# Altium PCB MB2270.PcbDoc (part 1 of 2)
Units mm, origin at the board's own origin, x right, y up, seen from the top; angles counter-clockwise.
Board outline 55.25 x 31 mm, 4 copper layers (Top Layer, Layer 1, Layer 2, Bottom Layer), stack 0.598 mm thick; 43 components, 44 nets, 187 pads, 892 vias.
Unrouted connection lines stored in the file: 111.
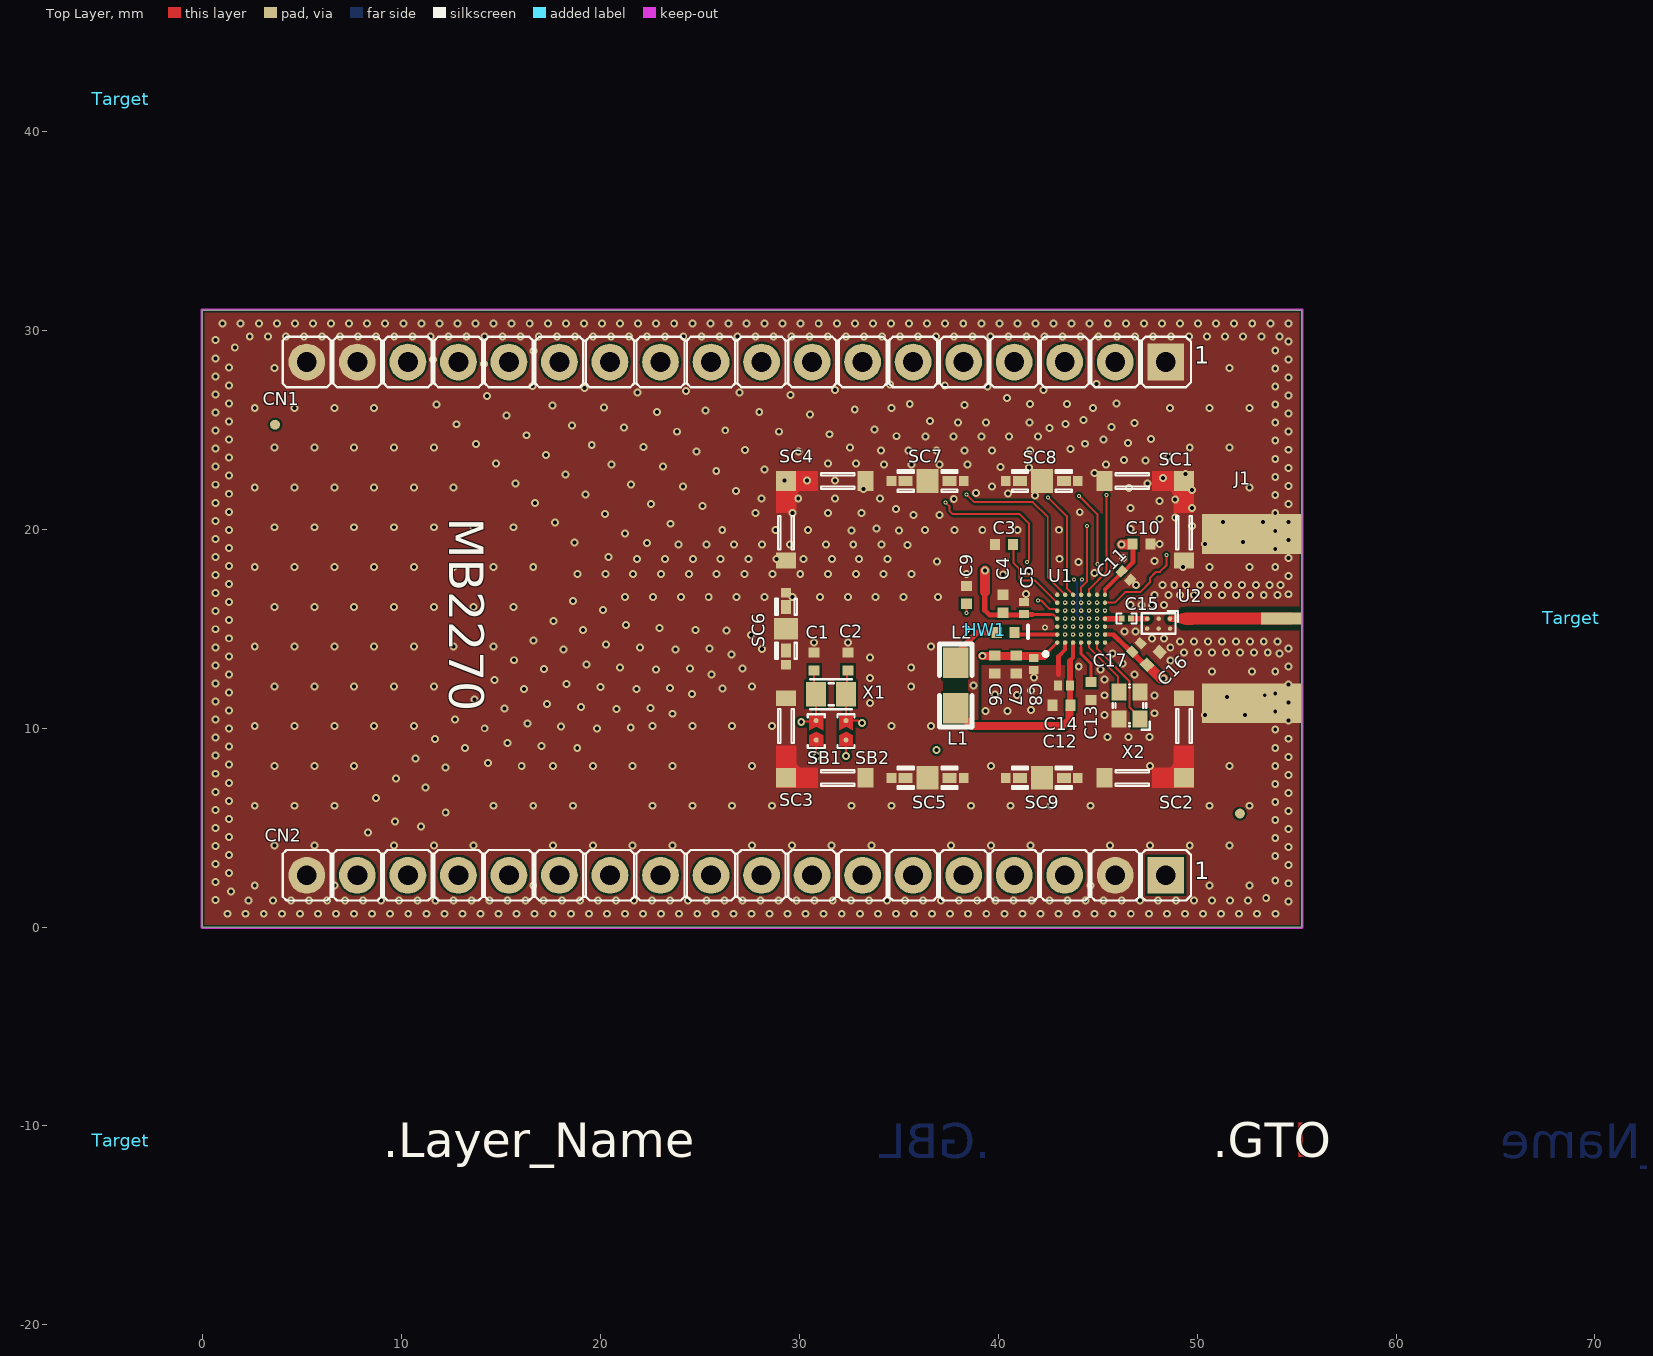
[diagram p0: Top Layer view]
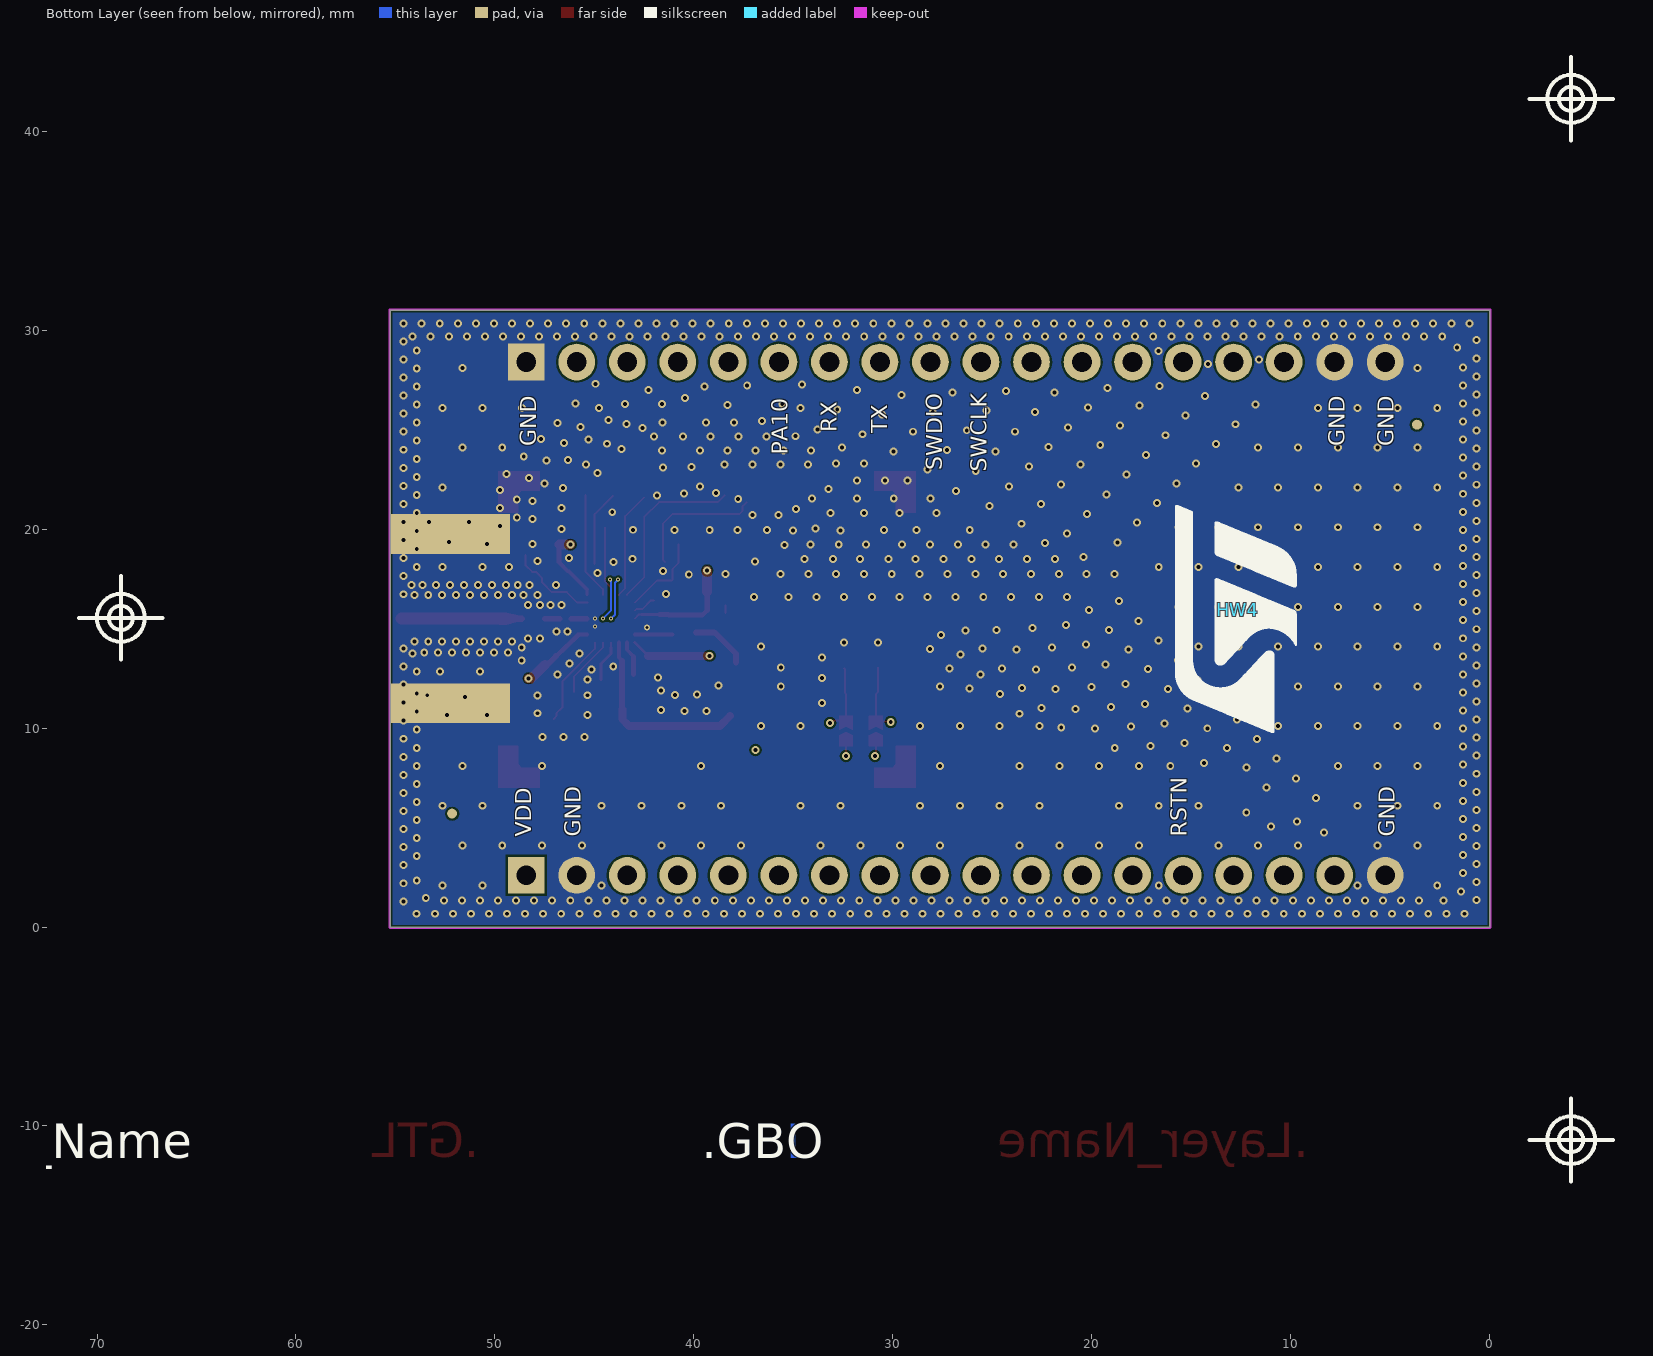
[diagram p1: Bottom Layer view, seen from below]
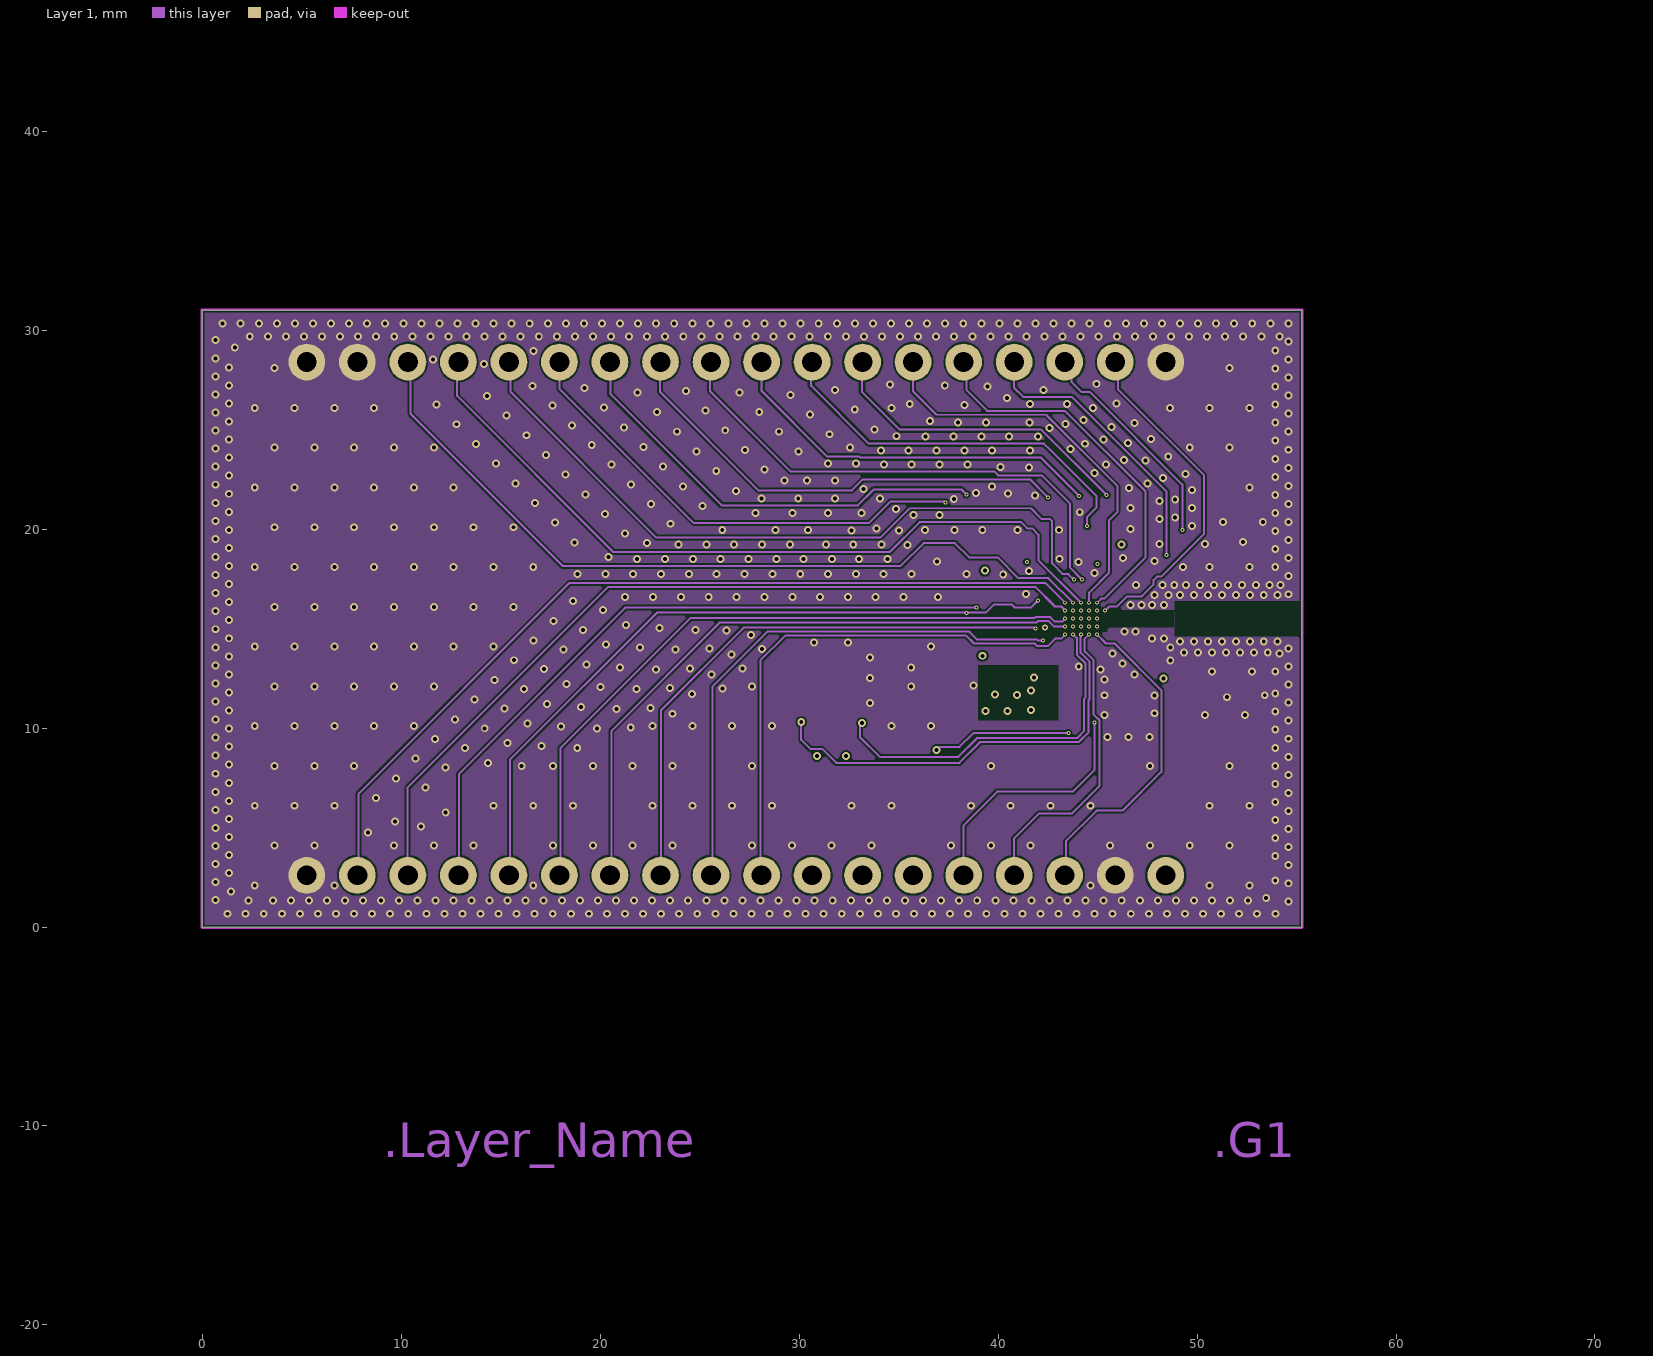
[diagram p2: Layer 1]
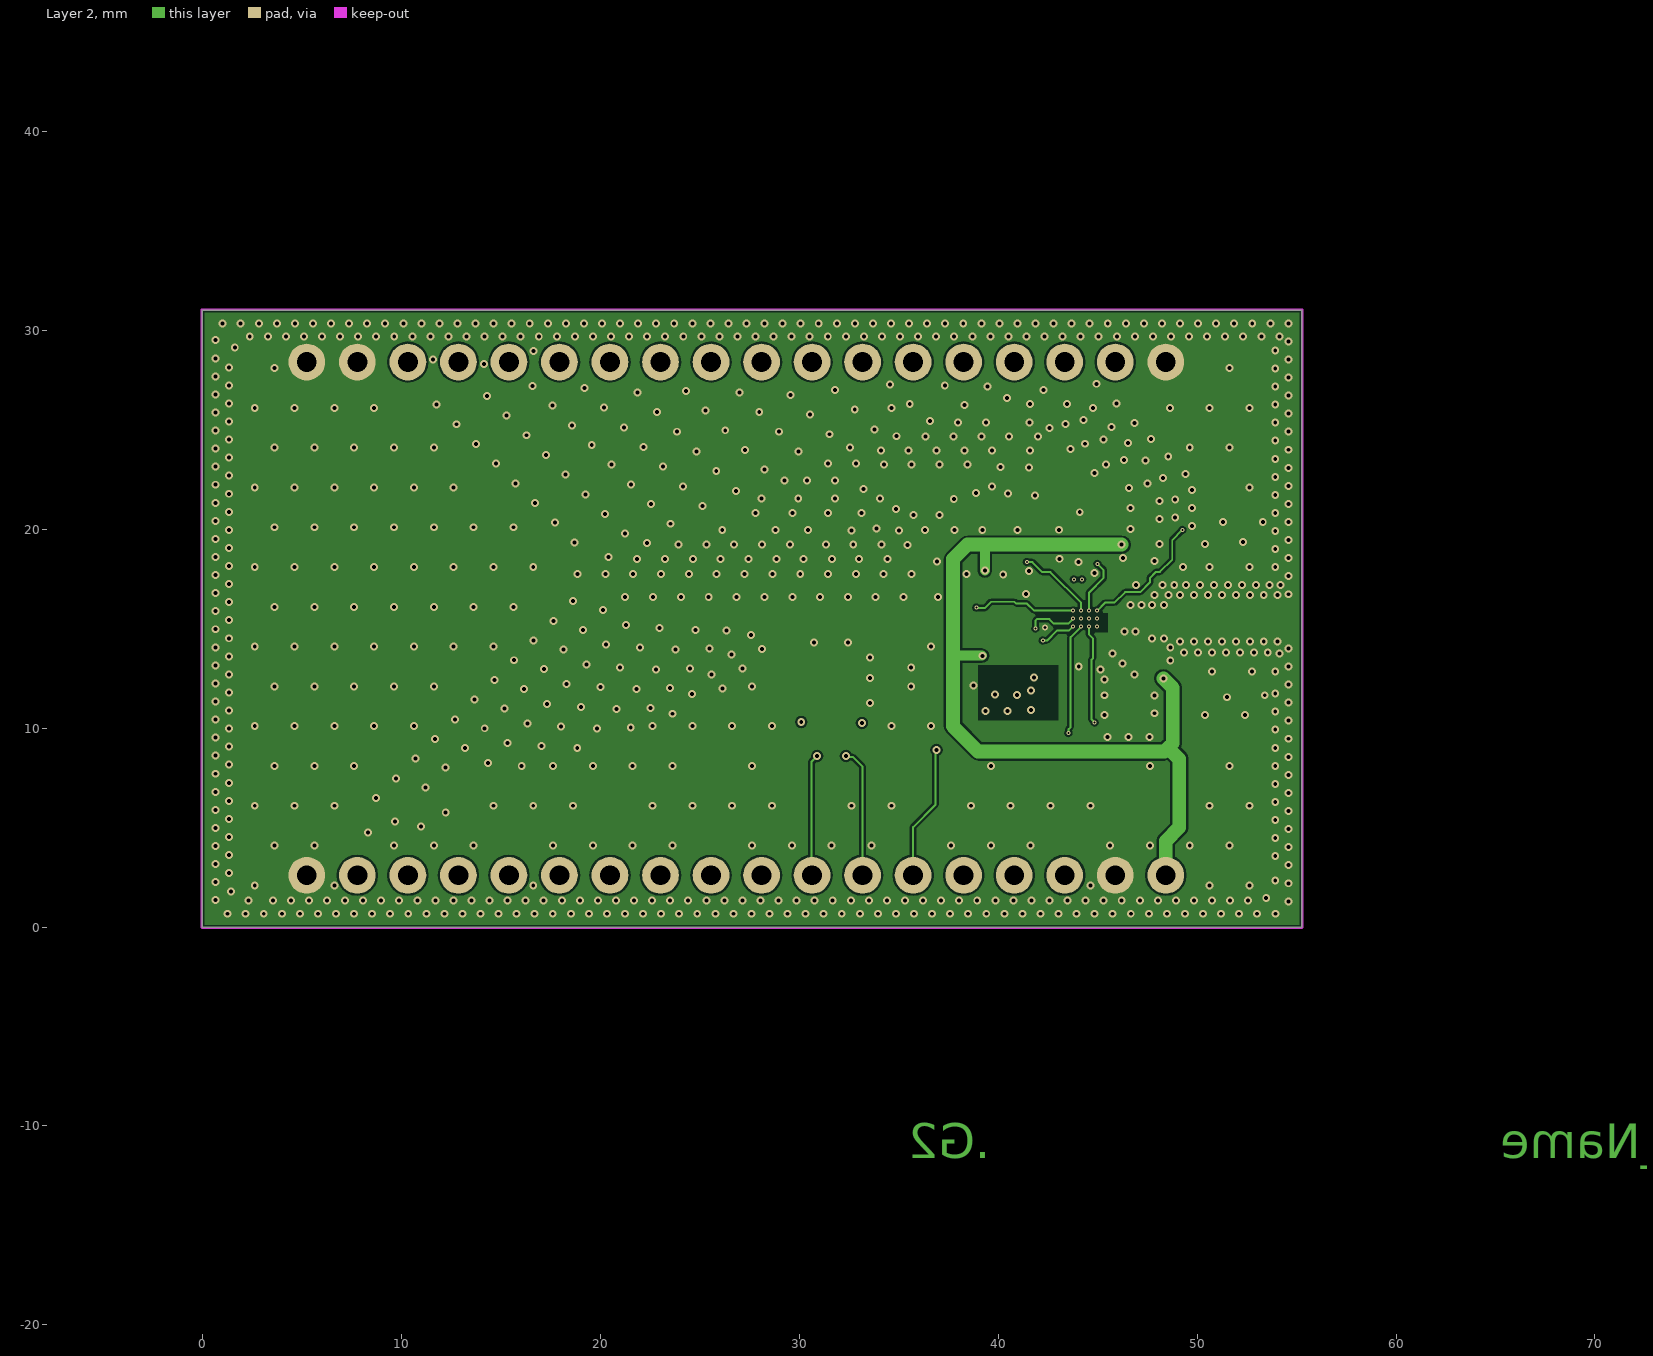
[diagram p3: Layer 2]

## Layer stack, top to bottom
Top Solder: solder mask 0.02, Solder Resist, Dk 3.5
Top Layer: signal copper 0.035
Dielectric 2: prepreg 0.102, TU-768 (1x2113), Dk 4.2
Layer 1: signal copper 0.035
Dielectric 1: dielectric 0.254, TU-768 (2x2116), Dk 4.3
Layer 2: signal copper 0.035
Dielectric 3: prepreg 0.102, TU-768 (1x2113), Dk 4.2
Bottom Layer: signal copper 0.035
Bottom Solder: solder mask 0.02, Solder Resist, Dk 3.5

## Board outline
0,0 55.25,0 55.25,31 0,31

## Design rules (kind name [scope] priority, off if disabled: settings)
Clearance Clearance_RF [InNet('NetJ1_1')] p1: gap=0.14 ignorepadtopadclearanceinfootprint=FALSE
Clearance [All] p2: gap=0.1 ignorepadtopadclearanceinfootprint=FALSE
HoleToHoleClearance [All] p1: gap=0.15 allowstackedmicrovias=TRUE
MinimumSolderMaskSliver [All] p1: minsoldermaskwidth=0
ParallelSegment [All] p1 off: limit=10 gap=0.3
PlaneClearance [All] p1: clearance=0
PlaneConnect [InNet('GND')] p1: planeconnectstyle=Direct reliefexpansion=0.508 reliefentries=4 reliefconductorwidth=0.254 reliefairgap=0.254
PolygonConnect [InNet('GND')] p1: connectstyle=Direct reliefconductorwidth=0.254 reliefentries=4 polygonreliefangle="90 Angle" airgapwidth=0.254
RoutingVias [All] p1: holewidth=0.2 width=0.4 viastyle="Through Hole" minholewidth=0.2 minwidth=0.4 maxholewidth=0.2 maxwidth=0.4
SilkToSilkClearance [All] p1: silktosilkclearance=0
SilkToSolderMaskClearance [IsPad] p1: minsilkscreentomaskgap=0 clearancetoexposedcopper=TRUE
SolderMaskExpansion [All] p1: expansion=0.102 istentingtop=FALSE
SupplyNets "Schematic Supply Nets" [InNet('VDD')] p1: voltage=0.000
Width [All] p1: maxlimit=0.7 minlimit=0.1 preferedwidth=0.1
24 further rules are at their usual default settings.

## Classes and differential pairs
component class STM32WB07_WLCSP49_RefBoard_IPD_4Layers: C1 C2 C3 C4 C5 C6 C7 C8 C9 C10 C11 C12 C13 C14 C15 C16 C17 CN1 CN2 J1 L1 L2 SB1 SB2 SC1 SC2 SC3 SC4 SC5 SC6 SC7 SC8 SC9 U1 U2 X1 X2

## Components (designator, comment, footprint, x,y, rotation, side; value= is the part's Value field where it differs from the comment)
C1 "Capacitor" C0402 30.75,13.35 r90 top value=8.2pF
C2 "Capacitor" C0402 32.45,13.35 r270 top value=8.2pF
C3 "Capacitor" C0402 40.297,19.219 r180 top value=0.22uF
C4 "Capacitor" C0402 40.25,16.25 r270 top value=1uF
C5 "Capacitor" C0201_H0P3 41.293,16.039 r270 top value=100nF
C6 "Capacitor" C0402 39.827,13.2 r90 top value=4.7uF
C7 "Capacitor" C0402 40.907,13.2 r90 top value=4.7uF
C8 "Capacitor" C0201_H0P3 41.788,13.219 r90 top value=100nF
C9 "Capacitor" C0402 38.4,16.7 r90 top value=10nF
C10 "Capacitor" C0402 47.2,19.25 r180 top value=1uF
C11 "Capacitor" C0201_H0P3 46.42,17.66 r135 top value=100nF
C12 "Capacitor" C0402 43.18,11.15 r0 top value=4.7uF
C13 "Capacitor" C0402 44.658,11.862 r270 top value=0.22uF
C14 "Capacitor" C0201_H0P3 43.3,12.15 r0 top value=100nF
C15 "Capacitor" 20p_capacitor_SMD_0201 46.444,15.5 r90 top locked value=20pF
C16 "Capacitor" C0402 47.8,13.5 r225 top value=1uF
C17 "Capacitor" C0201_H0P3 46.95,14.05 r225 top value=100nF
CN1 "Header 18x1" CON_SAMTEC_TSW-118-07-X-S 26.835,28.4 r180 top locked
CN2 "Header 18x1" CON_SAMTEC_TSW-118-07-X-S 26.835,2.6 r180 top locked
Designator16 "Comment" IMPEDANCE_TABLE 92.539,-28.797 r0 top
HW1 "S02-20150300" SHIELD_HARWIN_S02-20150300_15X20_H3 39.34,14.95 r90 top
HW4 "Logo" LOGO_ST 12.65,15.95 r90 bottom
J1 "SMA_connector" SMA_AMPHENOL_132415 54.225,15.5 r180 top
L1 "Inductor" 0805_COIL 37.869,10.999 r90 top value=10uH
L2 "Inductor" C0402 40.378,14.809 r0 top value=22nH
SB1 "SB_ON" SOLDER-BRIDGE_R0402-0R 30.85,9.85 r90 top value=0R
SB2 "SB_ON" SOLDER-BRIDGE_R0402-0R 32.35,9.85 r90 top value=0R
SC1 "Shield-clip_S0951-46R" CLIP_HARWIN_S0981-46R 49.337,22.418 r90 top locked value=S0981-46R
SC2 "Shield-clip_S0951-46R" CLIP_HARWIN_S0981-46R 49.337,7.5 r0 top locked value=S0981-46R
SC3 "Shield-clip_S0951-46R" CLIP_HARWIN_S0981-46R 29.337,7.5 r270 top locked value=S0981-46R
SC4 "Shield-clip_S0951-46R" CLIP_HARWIN_S0981-46R 29.337,22.418 r180 top locked value=S0981-46R
SC5 "Shield-clip_S0951-46R" CLIP_HARWIN_S0951-46R 36.448,7.5 r180 top locked value=S0951-46R
SC6 "Shield-clip_S0951-46R" CLIP_HARWIN_S0951-46R 29.337,14.993 r270 top locked value=S0951-46R
SC7 "Shield-clip_S0951-46R" CLIP_HARWIN_S0951-46R 36.448,22.418 r180 top locked value=S0951-46R
SC8 "Shield-clip_S0951-46R" CLIP_HARWIN_S0951-46R 42.198,22.418 r180 top locked value=S0951-46R
SC9 "Shield-clip_S0951-46R" CLIP_HARWIN_S0951-46R 42.198,7.5 r180 top locked value=S0951-46R
Target "" "Target PCB" -4.1,41.628 r90 top
Target "" "Target PCB" 68.8,15.54 r90 top
Target "" "Target PCB" -4.1,-10.71 r90 top
U1 "STM32WB07" STM32WB07_WLCSP49 44.169,15.5 r90 top locked
U2 "MLPF-WB55-01E3" ICC_CSPG_6BUMPS_1X1P60_P050-P0577 48.066,15.25 r270 top locked value=MLPF-NRG-01D3
X1 "XTAL_2_PINS" CRY_NX2012SA_2P 31.6,11.703 r0 top value=32.768kHz
X2 "XTAL_4_PINS" CRY_NX2016SA_4P 46.6,11.138 r90 top value=32MHz

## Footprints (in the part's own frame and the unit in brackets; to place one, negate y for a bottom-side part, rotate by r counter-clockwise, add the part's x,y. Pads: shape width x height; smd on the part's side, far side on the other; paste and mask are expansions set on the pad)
20p_capacitor_SMD_0201 [mm] "SMD 0201"
  rect 0.3x0.28 smd mask+0.05: 1(0.002,0.238) 2(0.002,-0.232)
  silkscreen extent -0.25,-0.51 0.25,0.51, body extent -0.15,-0.3 0.15,0.3, height 0.3
0805_COIL [mil]
  rect 60x50 smd: 1(0,0) 2(90,0)
  silkscreen extent -37,-32 127,32, body extent 6,-21 85,21, height 39
C0201_H0P3 [mm]
  rect 0.4x0.5 smd mask+0.05: 1(-0.3,0) 2(0.3,0)
  body extent -0.32,-0.17 0.32,0.17, height 0.33
C0402 [mm]
  rect 0.51x0.56 smd mask+0.05: 1(-0.45,0) 2(0.45,0)
  body extent -0.5,-0.3 0.5,0.3, height 0.4
CLIP_HARWIN_S0951-46R [mm] "MCD-01587_CLIP-X1"
  rect 0.48x0.5 smd mask+0.1: 1(-1.81,0) 1(1.81,0)
  rect 0.7x0.5 smd mask+0.1: 1(-1.1,0) 1(1.1,0)
  rect 1.1x1.2 smd mask+0.1: 1(0,0)
  silkscreen extent -1.5,-0.55 1.5,0.55, body extent -2.05,-0.65 2.05,0.65, height 1.28
CLIP_HARWIN_S0981-46R [mm] "MCD-02164"
  rect 0.8x1 smd mask+0.05: 1(-4,0)
  rect 1x0.8 smd mask+0.05: 1(0,4)
  rect 1x1 smd mask+0.05: 1(0,0)
  Top Layer region: -1.6,-0.5 0.5,-0.5 0.5,1.6 -0.5,1.6 -0.5,0.7 -0.7,0.5 -1.6,0.5
  silkscreen extent -3.45,-0.4 0.4,3.45, body extent -4.3,-0.46 0.46,4.3, height 1.4
CON_SAMTEC_TSW-118-07-X-S [mm] "MCD-01897"
  rect 1.85x1.85 / inner round 1.85 / far side rect 1.85x1.85 hole 1 mask+0.05: 1(-21.59,0)
  round 1.85 hole 1 mask+0.05: 2(-19.05,0) 3(-16.51,0) 4(-13.97,0) 5(-11.43,0) 6(-8.89,0) 7(-6.35,0) 8(-3.81,0) 9(-1.27,0) 10(1.27,0) 11(3.81,0) 12(6.35,0) 13(8.89,0) 14(11.43,0) 15(13.97,0) 16(16.51,0) 17(19.05,0) 18(21.59,0)
  silkscreen extent -22.86,-1.27 22.8,1.27, body extent -22.99,-1.27 22.86,1.27, height 8.38
CRY_NX2012SA_2P [mm]
  rect 1x1.25 smd mask+0.05: 1(-0.75,0) 2(0.75,0)
  silkscreen extent -1.05,-0.75 1.05,0.75, body extent -1.05,-0.63 1.05,0.63, height 0.6
CRY_NX2016SA_4P [mm]
  rect 0.85x0.75 smd mask+0.05: 1(-0.675,-0.525) 2(0.675,-0.525) 3(0.675,0.525) 4(-0.675,0.525)
  silkscreen extent -1.22,-1.02 1.05,0.85, body extent -1.05,-0.85 1.05,0.85, height 0.7
ICC_CSPG_6BUMPS_1X1P60_P050-P0577 [mm] "MCD-03490"
  round 0.22 smd paste+0 mask+0: A1(-0.25,0.577) A2(-0.25,0) A3(-0.25,-0.577) B1(0.25,0.577) B2(0.25,0) B3(0.25,-0.577)
  silkscreen extent -0.64,-0.85 0.51,0.97, body extent -0.51,-0.81 0.51,0.81, height 0.7
IMPEDANCE_TABLE [mm]
LOGO_ST [mm]
  silkscreen extent -6.18,-2.95 5.25,3.14
SHIELD_HARWIN_S02-20150300_15X20_H3 [mm] "MCD-03126"
  body extent -7.6,-10.1 7.6,10.1, height 3.25
SMA_AMPHENOL_132415 [mm]
  rect 2.05x0.6 smd mask+0: 1(0,0)
  rect 5x2 smd: 2(1.475,4.25) 2(1.475,-4.25)
  rect 6x2 smd far side: 2(1.975,4.25) 2(1.975,-4.25)
  body extent -10.55,-4.76 4.36,4.76, height 4.11
SOLDER-BRIDGE_R0402-0R [mil] "MCD-01619"
  round 10 smd paste-393.7: 1(-17.72,0) 2(20.67,0)
  Top Layer region: -30.51,-13.78 -30.51,13.78 -8.37,13.78 -1.48,0 -8.37,-13.78
  Top Layer region: 1.48,13.78 8.37,0 1.48,-13.78 30.51,-13.78 30.51,13.78
  silkscreen extent -33,-17 33,17, body extent -20,-12 20,12, height 14
STM32WB07_WLCSP49 [mm] "CSP49, 49-Leads, Body 3.14x3.14mmx0.42mm, Pitch 0.40mm"
  round 0.225 smd paste+0 mask+0.05: A1(-1.2,1.2)
  round 0.225 smd mask+0.05: A2(-0.8,1.2) A3(-0.4,1.2) A4(0,1.2) A5(0.4,1.2) A6(0.8,1.2) A7(1.2,1.2) B1(-1.2,0.8) B2(-0.8,0.8) B3(-0.4,0.8) B4(0,0.8) B5(0.4,0.8) B6(0.8,0.8) B7(1.2,0.8) C1(-1.2,0.4) C2(-0.8,0.4) C3(-0.4,0.4) C4(0,0.4) C5(0.4,0.4) C6(0.8,0.4) C7(1.2,0.4) D1(-1.2,0) D2(-0.8,0) D3(-0.4,0) D4(0,0) D5(0.4,0) D6(0.8,0) D7(1.2,0) E1(-1.2,-0.4) E2(-0.8,-0.4) E3(-0.4,-0.4) E4(0,-0.4) E5(0.4,-0.4) E6(0.8,-0.4) E7(1.2,-0.4) F1(-1.2,-0.8) F2(-0.8,-0.8) F3(-0.4,-0.8) F4(0,-0.8) F5(0.4,-0.8) F6(0.8,-0.8) F7(1.2,-0.8) G1(-1.2,-1.2) G2(-0.8,-1.2) G3(-0.4,-1.2) G4(0,-1.2) G5(0.4,-1.2) G6(0.8,-1.2) G7(1.2,-1.2)
  silkscreen extent -1.88,1.68 -1.68,1.88, body extent -1.58,-1.58 1.58,1.58, height 0.25
"Target PCB" [mm] "TargetA"

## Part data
C1 C2: library part MCD-03429, "Capacitor, MLCC, 8.2 pF, NPO, COG, 50V, +/-0.1pF, 0402, T=0.5mm", Manufacturer=MURATA, Manufacturer_Part_Number=GJM1555C1H8R2BB01D, Package=0402
C3 C13: library part MCD-03483, "Capacitor, MLCC, 0.22uF, X5R, 6.3V, +/-10%, 0402, T=0.5mm", Manufacturer=YAGEO, Manufacturer_Part_Number=CC0402KRX5R5BB224, Package=0402
C4 C10 C16: library part MCD-03432, "Capacitor, MLCC, 1uF, X7R, 6.3V,+/- 10%, 0402, T=0.5mm", Manufacturer=MURATA, Manufacturer_Part_Number=GRM155R70J105KA12, Package=0402
C5 C8 C11 C14 C17: library part MCD-01535, "Capacitor, MLCC,100nF, 10V, X5R, +/-10%, 0201, T=0.3mm", Manufacturer=MURATA, Manufacturer_Part_Number=GRM033R61A104KE15, Package=0201
C6 C7 C12: library part MCD-03431, "Capacitor, MLCC, 4.7uF, X5R, 10V, +/-20%, 0402, T=0.5mm", Manufacturer=MURATA, Manufacturer_Part_Number=GRM155R61A475MEAAD, Package=0402
C9: library part MCD-00011, "Capacitor, MLCC, 10nF, 16V, X7R, +/-10%, 0402, T=0.5mm", Manufacturer=YAGEO, Manufacturer_Part_Number=CC0402KRX7R7BB103, Package=0402
C15: library part MCD-03543, "Capacitor, MLCC, 20pF, 25V, COG, +/-2%, 0201, T=0.3mm", Manufacturer=MURATA, Manufacturer_Part_Number=GJM0335C1E200GB01, Package=0201
CN1 CN2: library part MCD-01897, "Header, 18x1, 2.54mm, VR, TH, T=5.84mm/8.38mm", Manufacturer=SAMTEC, Manufacturer_Part_Number=TSW-118-07-L-S, Package=TSW
Designator16: library part MCD-00279
HW1: library part MCD-03126, "RFI shield can, 20x15x3mm", Manufacturer=HARWIN, Package=20x15x3mm
HW4: library part MCD-00625, "\"STMicroelectronics\" logo footprint for PCB"
J1: "Rf Connector, Sma End Launch Recept Jack For .032\" Pcb / Individual Bag", Manufacturer="Amphenol Connex", Manufacturer Part Number=132415, Supplier Part Number 1=132415-ND
L1: library part MCD-03438, "Inductor, MLCC, 10uH, +/-20%, 300mA, 845mR, 0805, T=1.45mm", Manufacturer=MURATA, Manufacturer_Part_Number=LQM21DN100M70L, Package=0805
L2: library part MCD-03439, "Inductor, MLCC, 22nH, +/-2%, 350mA, 0.58R, 0402, T=1.45mm", Manufacturer=MURATA, Manufacturer_Part_Number=LQG15HN22NG02D, Package=0402
SB1 SB2: library part MCD-01618, "Resistor, 0R, SB0402, 5%, 0.063W", Manufacturer=YAGEO, Manufacturer_Part_Number=RC0402JR-070RL, Package=0402
SC1 SC2 SC3 SC4: library part MCD-02164, "Shield clip Harwin S0981-46R to fix RF shielded cavity", Manufacturer=HARWIN, Manufacturer_Part_Number=S0981-46R, Package=0.8x4.7x1.4mm
SC5 SC6 SC7 SC8 SC9: library part MCD-01587, "RFI shield clip mini TIN SMD", Manufacturer=HARWIN, Manufacturer_Part_Number=S0951-46R, Package=1.1x3.9mm
U1: library part STM32WB07_WLCSP49, "IC, Bluetooth Low Energy wireless SoC, WLCSP49"
U2: library part MCD-03490, "2.4 GHz low pass filter matched to BLUENRG-LP-LPS", Manufacturer=STMICROELECTRONICS, Manufacturer_Part_Number=MLPF-NRG-01D3, Package=CSP
X1: library part MCD-01445, "Crystal, 32.768kHz, 7pF, +/-20ppm, 80K, 2.05x1.2mm", Manufacturer=NDK, Manufacturer_Part_Number="NX2012SE 32.768kHz EXS00A-MU01259", Package=2.05x1.2mm
X2: library part MCD-01446, "Crystal, 32MHz, 8pF, +/-10ppm, 60R, 2x1.6mm", Manufacturer=NDK, Manufacturer_Part_Number=NX2016SA-32MHZ-EXS00A-CS06654, Package=2x1.6mm

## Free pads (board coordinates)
  round 0.5 smd paste+0 mask+0: 1(3.65,25.25)
  round 0.5 smd far side paste+0 mask+0: 1(3.65,25.25)
  round 0.508 on Mech16: 1(20.768,-18.512) 1(69.616,-18.512)
  round 0.5 smd mask+0: 1(52.15,5.7)
  round 0.5 smd far side mask+0: 1(52.15,5.7)

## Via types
v1: diameter 0.4, hole 0.2, Top Layer to Bottom Layer, tented both sides, 846 vias
v2: diameter 0.2, hole 0.1, Top Layer to Layer 1, tented top, 23 vias
v3: diameter 0.2, hole 0.1, Top Layer to Layer 2, tented top, 10 vias
v4: diameter 0.2, hole 0.1, Layer 1 to Layer 2, tented top, 6 vias
v5: diameter 0.2, hole 0.1, Top Layer to Bottom Layer, tented both sides, 6 vias
v6: diameter 0.3, hole 0.15, Top Layer to Bottom Layer, tented both sides, 1 vias

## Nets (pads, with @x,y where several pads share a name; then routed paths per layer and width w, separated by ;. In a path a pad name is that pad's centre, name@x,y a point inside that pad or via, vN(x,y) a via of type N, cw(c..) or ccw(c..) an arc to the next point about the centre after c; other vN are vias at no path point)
GND: C1.2 C2.1 C3.2 C4.1 C5.1 C6.1 C7.1 C8.1 C9.2 C10.1 C11.1 C12.1 C13.2 C14.1 C16.1 C17.1 CN1.1 CN1.17 CN1.18 CN2.2 CN2.18 J1.2 SC1.1 SC2.1 SC3.1 SC4.1 SC5.1 SC6.1 SC7.1 SC8.1 SC9.1 U1.A3 U1.A7 U1.B1 U1.F3 U1.F4 U1.F7 U1.G1 U1.G3 U2.A2 U2.B1 U2.B2 U2.B3 X2.2 X2.4 | length 1.8
  Top Layer w0.2: 43.026,13.595 43.369,13.938 U1.B1@43.369,14.3
  Top Layer w0.25: 43.026,12.686 43.026,13.595
  other v1: 1.265,0.666 2.173,0.666 3.081,0.666 3.989,0.666 4.897,0.666 5.805,0.666 6.713,0.666 7.621,0.666 8.529,0.666 9.437,0.666 10.345,0.666 11.253,0.666 12.161,0.666 13.069,0.666 13.977,0.666 14.885,0.666 15.793,0.666 16.701,0.666 17.609,0.666 18.517,0.666 19.425,0.666 20.333,0.666 21.241,0.666 22.149,0.666 23.057,0.666 23.965,0.666 24.873,0.666 25.781,0.666 26.689,0.666 27.597,0.666 28.505,0.666 29.413,0.666 30.321,0.666 31.229,0.666 32.137,0.666 33.045,0.666 33.953,0.666 34.861,0.666 35.769,0.666 36.677,0.666 37.585,0.666 38.493,0.666 39.401,0.666 40.309,0.666 41.217,0.666 42.125,0.666 43.033,0.666 43.941,0.666 44.849,0.666 45.757,0.666 46.665,0.666 47.573,0.666 48.481,0.666 49.389,0.666 50.297,0.666 51.205,0.666 52.113,0.666 53.021,0.666 53.929,0.666 54.588,1.291 2.322,1.325 3.535,1.325 4.443,1.325 5.351,1.325 6.259,1.325 7.167,1.325 8.075,1.325 8.983,1.325 9.891,1.325 10.799,1.325 11.707,1.325 12.615,1.325 13.523,1.325 14.431,1.325 15.339,1.325 16.247,1.325 17.155,1.325 18.063,1.325 18.971,1.325 19.879,1.325 20.787,1.325 21.695,1.325 22.603,1.325 23.511,1.325 24.419,1.325 25.327,1.325 26.235,1.325 27.143,1.325 28.051,1.325 28.959,1.325 29.867,1.325 30.775,1.325 31.683,1.325 32.591,1.325 33.499,1.325 34.407,1.325 35.315,1.325 36.223,1.325 37.131,1.325 38.039,1.325 38.947,1.325 39.855,1.325 40.763,1.325 41.671,1.325 42.579,1.325 43.487,1.325 44.395,1.325 45.303,1.325 46.211,1.325 47.119,1.325 48.027,1.325 48.935,1.325 49.843,1.325 50.751,1.325 51.659,1.325 52.567,1.325 0.666,1.348 53.474,1.45 1.445,1.791 2.629,2.095 6.629,2.095 16.629,2.095 44.629,2.095 50.629,2.095 52.629,2.095 54.588,2.199 0.666,2.256 53.928,2.34 1.326,2.71 54.588,3.107 0.666,3.164 53.928,3.561 1.326,3.618 54.588,4.015 0.666,4.072 3.629,4.095 5.629,4.095 9.629,4.095 11.629,4.095 13.629,4.095 17.629,4.095 19.629,4.095 21.629,4.095 23.629,4.095 27.629,4.095 29.629,4.095 31.629,4.095 33.629,4.095 37.629,4.095 39.629,4.095 41.629,4.095 45.629,4.095 47.629,4.095 49.629,4.095 51.629,4.095 53.928,4.469 1.326,4.526 8.329,4.745 54.588,4.923 0.666,4.98 10.979,5.045 9.679,5.295 53.928,5.377 1.326,5.434 12.229,5.745 54.588,5.831 0.666,5.888 2.629,6.095 4.629,6.095 6.629,6.095 14.629,6.095 16.629,6.095 18.629,6.095 22.629,6.095 24.629,6.095 26.629,6.095 28.629,6.095 32.629,6.095 34.629,6.095 38.629,6.095 40.629,6.095 42.629,6.095 44.629,6.095 50.629,6.095 52.629,6.095 53.928,6.285 1.326,6.342 8.73,6.48 54.588,6.739 0.666,6.796 11.22,7.02 53.928,7.193 1.326,7.25 9.72,7.47 54.588,7.647 0.666,7.704 12.21,8.01 3.629,8.095 5.629,8.095 7.629,8.095 16.05,8.1 17.629,8.095 19.629,8.095 21.629,8.095 23.629,8.095 27.629,8.095 39.629,8.095 47.629,8.095 51.629,8.095 53.928,8.101 1.326,8.158 14.35,8.25 10.71,8.46 54.588,8.555 0.666,8.612 18.84,8.99 13.2,9 53.928,9.009 1.326,9.066 17.04,9.09 15.34,9.24 11.7,9.45 54.588,9.463 0.666,9.52 45.489,9.562 46.553,9.562 47.612,9.562 53.928,9.917 1.326,9.974 19.83,9.98 14.19,9.99 21.53,10.03 18.03,10.08 2.629,10.095 4.629,10.095 6.629,10.095 8.629,10.095 10.629,10.095 22.629,10.095 24.629,10.095 26.629,10.095 28.629,10.095 34.629,10.095 36.629,10.095 16.33,10.23 54.588,10.371 0.666,10.428 12.69,10.44 45.35,10.65 50.4,10.65 52.4,10.65 23.62,10.72 47.85,10.745 53.928,10.825 40.475,10.847 39.36,10.857 1.326,10.882 41.654,10.916 15.18,10.98 20.82,10.97 22.52,11.02 19.02,11.07 17.32,11.22 33.55,11.268 54.588,11.279 0.666,11.336 13.68,11.43 51.5,11.55 40.935,11.665 45.35,11.65 47.85,11.645 53.4,11.65 39.85,11.683 24.61,11.71 53.928,11.733 1.326,11.79 41.654,11.878 16.17,11.97 21.81,11.96 23.51,12.01 26.15,12 20.01,12.06 3.629,12.095 5.629,12.095 7.629,12.095 9.629,12.095 11.629,12.095 27.629,12.095 35.629,12.095 38.75,12.15 54.588,12.187 18.31,12.21 0.666,12.244 14.67,12.42 45.35,12.45 33.55,12.518 41.801,12.534 1.326,12.698 25.6,12.7 46.85,12.7 50.75,12.85 52.75,12.85 53.928,12.85 17.16,12.96 22.8,12.95 45.15,12.95 24.5,13 27.14,12.99 21,13.05 35.629,13.05 44.05,13.1 54.588,13.095 0.666,13.152 19.3,13.2 46.25,13.245 15.66,13.41 48.65,13.4 33.55,13.55 1.326,13.606 26.59,13.69 45.75,13.75 54.15,13.75 49.351,13.8 50.051,13.8 50.75,13.8 51.45,13.8 52.151,13.8 52.851,13.8 53.55,13.8 18.15,13.95 23.79,13.94 25.49,13.99 28.13,13.98 54.588,14.003 21.99,14.04 48.65,14.05 0.666,14.06 2.629,14.095 4.629,14.095 6.629,14.095 8.629,14.095 10.629,14.095 12.629,14.095 14.629,14.095 36.629,14.095 20.29,14.19 30.75,14.3 32.45,14.3 49.15,14.35 49.85,14.35 50.55,14.35 51.25,14.35 51.95,14.35 52.65,14.35 53.35,14.35 54.05,14.35 16.65,14.4 47.729,14.5 48.329,14.5 1.326,14.514 27.58,14.68 46.35,14.85 46.9,14.85 26.35,14.9 19.14,14.94 24.78,14.93 0.666,14.968 22.98,15.03 21.28,15.18 17.64,15.39 1.326,15.422 0.666,15.876 20.13,15.93 3.629,16.095 5.629,16.095 7.629,16.095 9.629,16.095 11.629,16.095 13.629,16.095 15.629,16.095 46.65,16.18 47.2,16.18 47.729,16.18 48.329,16.18 1.326,16.33 18.63,16.38 21.25,16.6 22.65,16.6 24.05,16.6 25.45,16.6 26.85,16.6 28.25,16.6 29.65,16.6 31.05,16.6 32.45,16.6 33.825,16.6 35.24,16.6 36.967,16.6 47.85,16.7 48.55,16.7 49.15,16.7 49.85,16.7 50.55,16.7 51.25,16.7 51.95,16.7 52.65,16.7 53.35,16.7 54.05,16.7 54.588,16.727 41.4,16.75 0.666,16.784 46.93,17.19 48.25,17.2 48.85,17.2 49.449,17.2 50.149,17.2 50.85,17.2 51.549,17.2 52.249,17.2 52.949,17.2 53.65,17.2 54.2,17.2 1.326,17.238 54.588,17.635 0.666,17.692 40.254,17.73 18.85,17.74 20.25,17.74 21.65,17.74 23.05,17.74 24.45,17.74 25.85,17.74 27.25,17.74 28.65,17.74 30.05,17.74 31.45,17.74 32.85,17.74 34.225,17.74 35.64,17.74 38.4,17.75 44.85,17.8 41.557,17.892 53.928,18.089 2.629,18.095 4.629,18.095 6.629,18.095 8.629,18.095 10.629,18.095 12.629,18.095 14.629,18.095 16.629,18.095 49.3,18.095 50.629,18.095 52.629,18.095 1.326,18.146 44.044,18.348 36.922,18.381 47.85,18.4 21.85,18.5 23.25,18.5 24.65,18.5 26.05,18.5 27.45,18.5 28.85,18.5 30.225,18.5 31.64,18.5 33.015,18.5 34.429,18.5 43.081,18.511 46.27,18.54 54.588,18.543 0.666,18.6 20.403,18.603 53.928,18.997 1.326,19.054 35.45,19.2 23.93,19.228 25.33,19.228 26.73,19.228 28.13,19.228 29.53,19.228 31.34,19.228 32.715,19.228 34.129,19.228 48.1,19.25 50.4,19.25 22.35,19.3 18.705,19.333 52.3,19.35 54.588,19.451 0.666,19.508 21.23,19.77 53.928,19.905 32.63,19.928 35.017,19.925 36.329,19.946 37.808,19.946 39.2,19.946 40.966,19.946 1.326,19.962 26.13,19.95 28.798,19.95 30.45,19.95 43.067,19.968 46.65,19.999 33.882,20.032 3.629,20.095 5.629,20.095 7.629,20.095 9.629,20.095 11.629,20.095 13.629,20.095 15.629,20.095 49.737,20.147 23.53,20.27 17.715,20.323 51.3,20.35 53.3,20.35 54.588,20.359 0.666,20.416 48.1,20.509 48.9,20.589 35.75,20.7 37.05,20.7 20.24,20.76 27.808,20.8 29.658,20.8 31.44,20.8 33.132,20.8 53.928,20.813 44.1,20.85 1.326,20.87 34.872,21.022 49.737,21.058 46.65,21.069 25.14,21.16 22.54,21.26 54.588,21.267 16.725,21.313 0.666,21.324 48.1,21.419 48.9,21.5 37.767,21.525 28.1,21.55 29.95,21.55 31.8,21.55 34.05,21.55 41.85,21.7 53.928,21.721 19.25,21.75 1.326,21.778 40.5,21.8 38.885,21.822 26.818,21.926 49.737,21.968 33.221,22.018 46.579,22.076 2.629,22.095 4.629,22.095 6.629,22.095 8.629,22.095 10.629,22.095 12.629,22.095 52.629,22.095 24.15,22.15 39.7,22.15 54.588,22.175 0.666,22.232 21.55,22.25 15.735,22.303 47.499,22.296 29.25,22.45 30.4,22.45 31.8,22.45 48.274,22.571 53.928,22.629 1.326,22.686 18.26,22.74 49.424,22.77 44.83,22.828 25.828,22.916 28.26,22.99 54.588,23.083 41.55,23.1 0.666,23.14 23.16,23.14 40.115,23.125 20.56,23.24 34.251,23.25 35.651,23.25 37.051,23.25 38.451,23.25 45.409,23.256 14.745,23.293 31.45,23.3 32.85,23.3 47.399,23.446 46.324,23.471 53.928,23.537 1.326,23.594 48.549,23.646 17.27,23.73 24.838,23.906 29.969,23.906 34.1,23.95 35.5,23.95 36.9,23.95 38.3,23.95 39.7,23.95 41.597,23.95 27.27,23.98 54.588,23.991 43.629,24.029 0.666,24.048 3.629,24.095 5.629,24.095 7.629,24.095 9.629,24.095 11.629,24.095 32.55,24.1 49.629,24.095 51.629,24.095 22.17,24.13 19.57,24.23 13.755,24.283 44.372,24.293 46.523,24.322 53.928,24.445 1.326,24.502 45.287,24.508 47.673,24.522 34.89,24.67 36.35,24.65 37.75,24.65 39.15,24.65 40.55,24.65 42,24.65 16.28,24.72 31.53,24.77 23.848,24.896 28.979,24.896 54.588,24.899 0.666,24.956 26.28,24.97 33.78,25.02 42.574,25.084 21.18,25.12 45.7,25.145 18.58,25.22 12.765,25.273 43.383,25.283 37.979,25.35 39.379,25.35 41.565,25.35 46.85,25.345 53.928,25.353 1.326,25.41 36.579,25.44 44.297,25.497 15.29,25.71 30.54,25.76 54.588,25.807 0.666,25.864 22.858,25.886 27.989,25.886 25.29,25.96 32.79,26.01 44.757,26.088 2.629,26.095 4.629,26.095 6.629,26.095 8.629,26.095 20.19,26.11 34.629,26.095 48.629,26.095 50.629,26.095 52.629,26.095 17.59,26.21 38.304,26.235 11.776,26.263 53.928,26.261 35.554,26.285 43.461,26.282 1.326,26.318 41.6,26.3 45.937,26.318 40.45,26.6 14.3,26.7 54.588,26.715 29.55,26.75 0.666,26.772 21.868,26.876 26.999,26.876 24.3,26.95 31.8,27 42.285,27 19.2,27.1 39.46,27.175 53.928,27.169 16.6,27.2 1.326,27.226 37.315,27.225 34.565,27.275 44.947,27.308 54.588,27.623 0.666,27.68 3.629,28.095 51.629,28.095 53.928,28.077 1.326,28.134 14.15,28.3 54.588,28.531 11.595,28.537 0.666,28.588 16.65,28.95 53.928,28.985 1.625,29.131 54.588,29.439 0.666,29.496 2.378,29.674 3.286,29.674 4.194,29.674 5.102,29.674 6.01,29.674 6.918,29.674 7.826,29.674 8.734,29.674 9.642,29.674 10.55,29.674 11.458,29.674 12.366,29.674 13.274,29.674 14.182,29.674 15.09,29.674 15.998,29.674 16.906,29.674 17.814,29.674 18.722,29.674 19.63,29.674 20.538,29.674 21.446,29.674 22.354,29.674 23.262,29.674 24.17,29.674 25.078,29.674 25.986,29.674 26.894,29.674 27.802,29.674 28.71,29.674 29.618,29.674 30.526,29.674 31.434,29.674 32.342,29.674 33.25,29.674 34.158,29.674 35.066,29.674 35.974,29.674 36.882,29.674 37.79,29.674 38.698,29.674 39.606,29.674 40.514,29.674 41.422,29.674 42.33,29.674 43.238,29.674 44.146,29.674 45.054,29.674 45.962,29.674 46.87,29.674 47.778,29.674 48.686,29.674 49.594,29.674 50.502,29.674 51.41,29.674 52.318,29.674 53.226,29.674 54.134,29.674 1.016,30.334 1.924,30.334 2.832,30.334 3.74,30.334 4.648,30.334 5.556,30.334 6.464,30.334 7.372,30.334 8.28,30.334 9.188,30.334 10.096,30.334 11.004,30.334 11.912,30.334 12.82,30.334 13.728,30.334 14.636,30.334 15.544,30.334 16.452,30.334 17.36,30.334 18.268,30.334 19.176,30.334 20.084,30.334 20.992,30.334 21.9,30.334 22.808,30.334 23.716,30.334 24.624,30.334 25.532,30.334 26.44,30.334 27.348,30.334 28.256,30.334 29.164,30.334 30.072,30.334 30.98,30.334 31.888,30.334 32.796,30.334 33.704,30.334 34.612,30.334 35.52,30.334 36.428,30.334 37.336,30.334 38.244,30.334 39.152,30.334 40.06,30.334 40.968,30.334 41.876,30.334 42.784,30.334 43.692,30.334 44.6,30.334 45.508,30.334 46.416,30.334 47.324,30.334 48.232,30.334 49.14,30.334 50.048,30.334 50.956,30.334 51.864,30.334 52.772,30.334 53.68,30.334 54.588,30.334
  other v5: 44.969,15.1 44.969,15.5
  other v6: 42.344,15.057
NetC1_1: C1.1 SB1.2 U1.D2 X1.1 | length 25.1
  Top Layer w0.1: v1@30.15,10.3 30.175,10.325 30.85,10.325 X1.1@30.85,11.703 30.75,11.803 C1.1@30.75,13.05
  Layer 1 w0.1: v1(30.1,10.3) 30.1,9.403 30.553,8.95 31.15,8.95 31.85,8.25 38.05,8.25 39.1,9.3 44.05,9.3 44.55,9.8 44.55,11.405 44.6,11.455 44.6,13.328 44.15,13.778 44.15,14.564 44.15,14.681 v2(44.169,14.7)
NetC2_2: C2.2 SB2.2 U1.C2 X1.2 | length 21.6
  Top Layer w0.1: SB2.2@32.35,10.325 X1.2@32.35,11.703 ; SB2.2@32.35,10.375 32.944,10.375 33.069,10.25 v1(33.15,10.25) ; X1.2@32.4,11.753 32.4,12.95 C2.2@32.45,13
  Layer 1 w0.1: v1@33.075,10.275 33.05,10.25 33.05,9.55 34.05,8.55 38.004,8.55 38.954,9.5 43.967,9.5 44.323,9.855 44.323,11.473 44.4,11.55 44.4,13.245 43.95,13.695 43.95,14.519 v2(43.769,14.7)
NetC3_1: C3.1 U1.A6 | length 4.3
  Top Layer w0.1: C3.1@40.759,19.219 40.759,18.304 41.062,18.002 41.062,17.471 41.123,17.41 41.859,17.41 U1.A6@42.969,16.3
NetC12_2: C12.2 C14.2 L1.1 U1.C1 | length 9.5
  Top Layer w0.2: 43.6,13.374 43.766,13.539 U1.C1@43.769,14.3
  Top Layer w0.3: C14.2@43.6,12.235 43.6,13.374 ; C12.2@43.618,11.086 C14.2@43.618,12.15
  Top Layer w0.4: L1.1@38.172,10.619 38.687,10.104 43.255,10.104 43.594,10.443 C12.2@43.594,10.944
NetC13_1: C13.1 U1.D1 | length 4.2
  Top Layer w0.1: 44.169,14.053 U1.D1@44.169,14.3 44.169,14.053
  Top Layer w0.15: 44.169,13.729 44.169,14.053 44.169,13.729 ; 44.169,13.729 44.658,13.24 ; 44.169,13.729 44.658,13.24 ; 44.658,13.24 44.658,12.427 44.658,13.24
NetC15_1: C15.1 U1.G4 | length 0.8
  Top Layer w0.275: U1.G4@45.369,15.5 C15.1@46.15,15.5
NetC15_2: C15.2 U2.A3 | length 0.7
  Top Layer w0.275: C15.2@46.75,15.5 U2.A3@47.487,15.5
NetJ1_1: J1.1 U2.A1 | length 5.4
  Top Layer w0.32: U2.A1@48.643,15.5 48.915,15.5
  Top Layer w0.6: 49.55,15.5 J1.1@54.7,15.5
NetL1_2: L1.2 L2.1 | length 2.9
  Top Layer w0.3: L1.2@37.869,13.285 37.869,13.722 38.954,14.807 L2.1@39.879,14.807
NetL2_2: L2.2 U1.A2 | length 1.9
  Top Layer w0.1: L2.2@41.07,14.698 L2.2@41.072,14.7
  Top Layer w0.2: L2.2@41.072,14.7 U1.A2@42.969,14.7
NetU1_E1: U1.E1 X2.3 | length 3.1
  Top Layer w0.1: U1.E1@44.569,14.3 44.569,14.042 46.014,12.597 X2.3@46.014,11.803
NetU1_F1: U1.F1 X2.1 | length 4.7
  Top Layer w0.1: U1.F1@44.969,14.3 44.969,13.98 46.6,12.35 46.6,11.048 46.907,10.741 46.907,10.6 47.053,10.453 X2.1@47.064,10.453
PA0: CN1.5 U1.F6 | length 18.9
  Layer 1 w0.1: CN1.5@38.291,28.082 38.4,27.974 38.4,27 39.45,25.95 43.35,25.95 47.409,21.891 47.409,18.584 45.326,16.501 45.17,16.501 v2(44.969,16.3)
PA1: CN1.4 U1.G6 | length 18.8
  Top Layer w0.1: U1.G6@45.346,16.306 45.352,16.3 U1.G6@45.369,16.3 45.849,16.3 46.386,16.836 47.14,16.836 47.62,17.316 47.62,17.54 47.932,17.852 48.13,17.852 48.45,18.172 v2(48.45,18.7)
  Layer 1 w0.1: CN1.4@40.805,28.4 40.805,27.095 41.25,26.65 43.7,26.65 48.45,21.9 v2(48.45,18.7)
